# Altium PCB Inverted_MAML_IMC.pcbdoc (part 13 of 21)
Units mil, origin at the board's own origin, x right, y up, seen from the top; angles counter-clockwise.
Board outline 7677.1 x 6771.6 mil, 6 copper layers (Top Layer, Inner1, Inner2, Inner3, Inner4, Bottom Layer), stack 60.7 mil thick; 2732 components, 1531 nets, 7765 pads, 3705 vias.
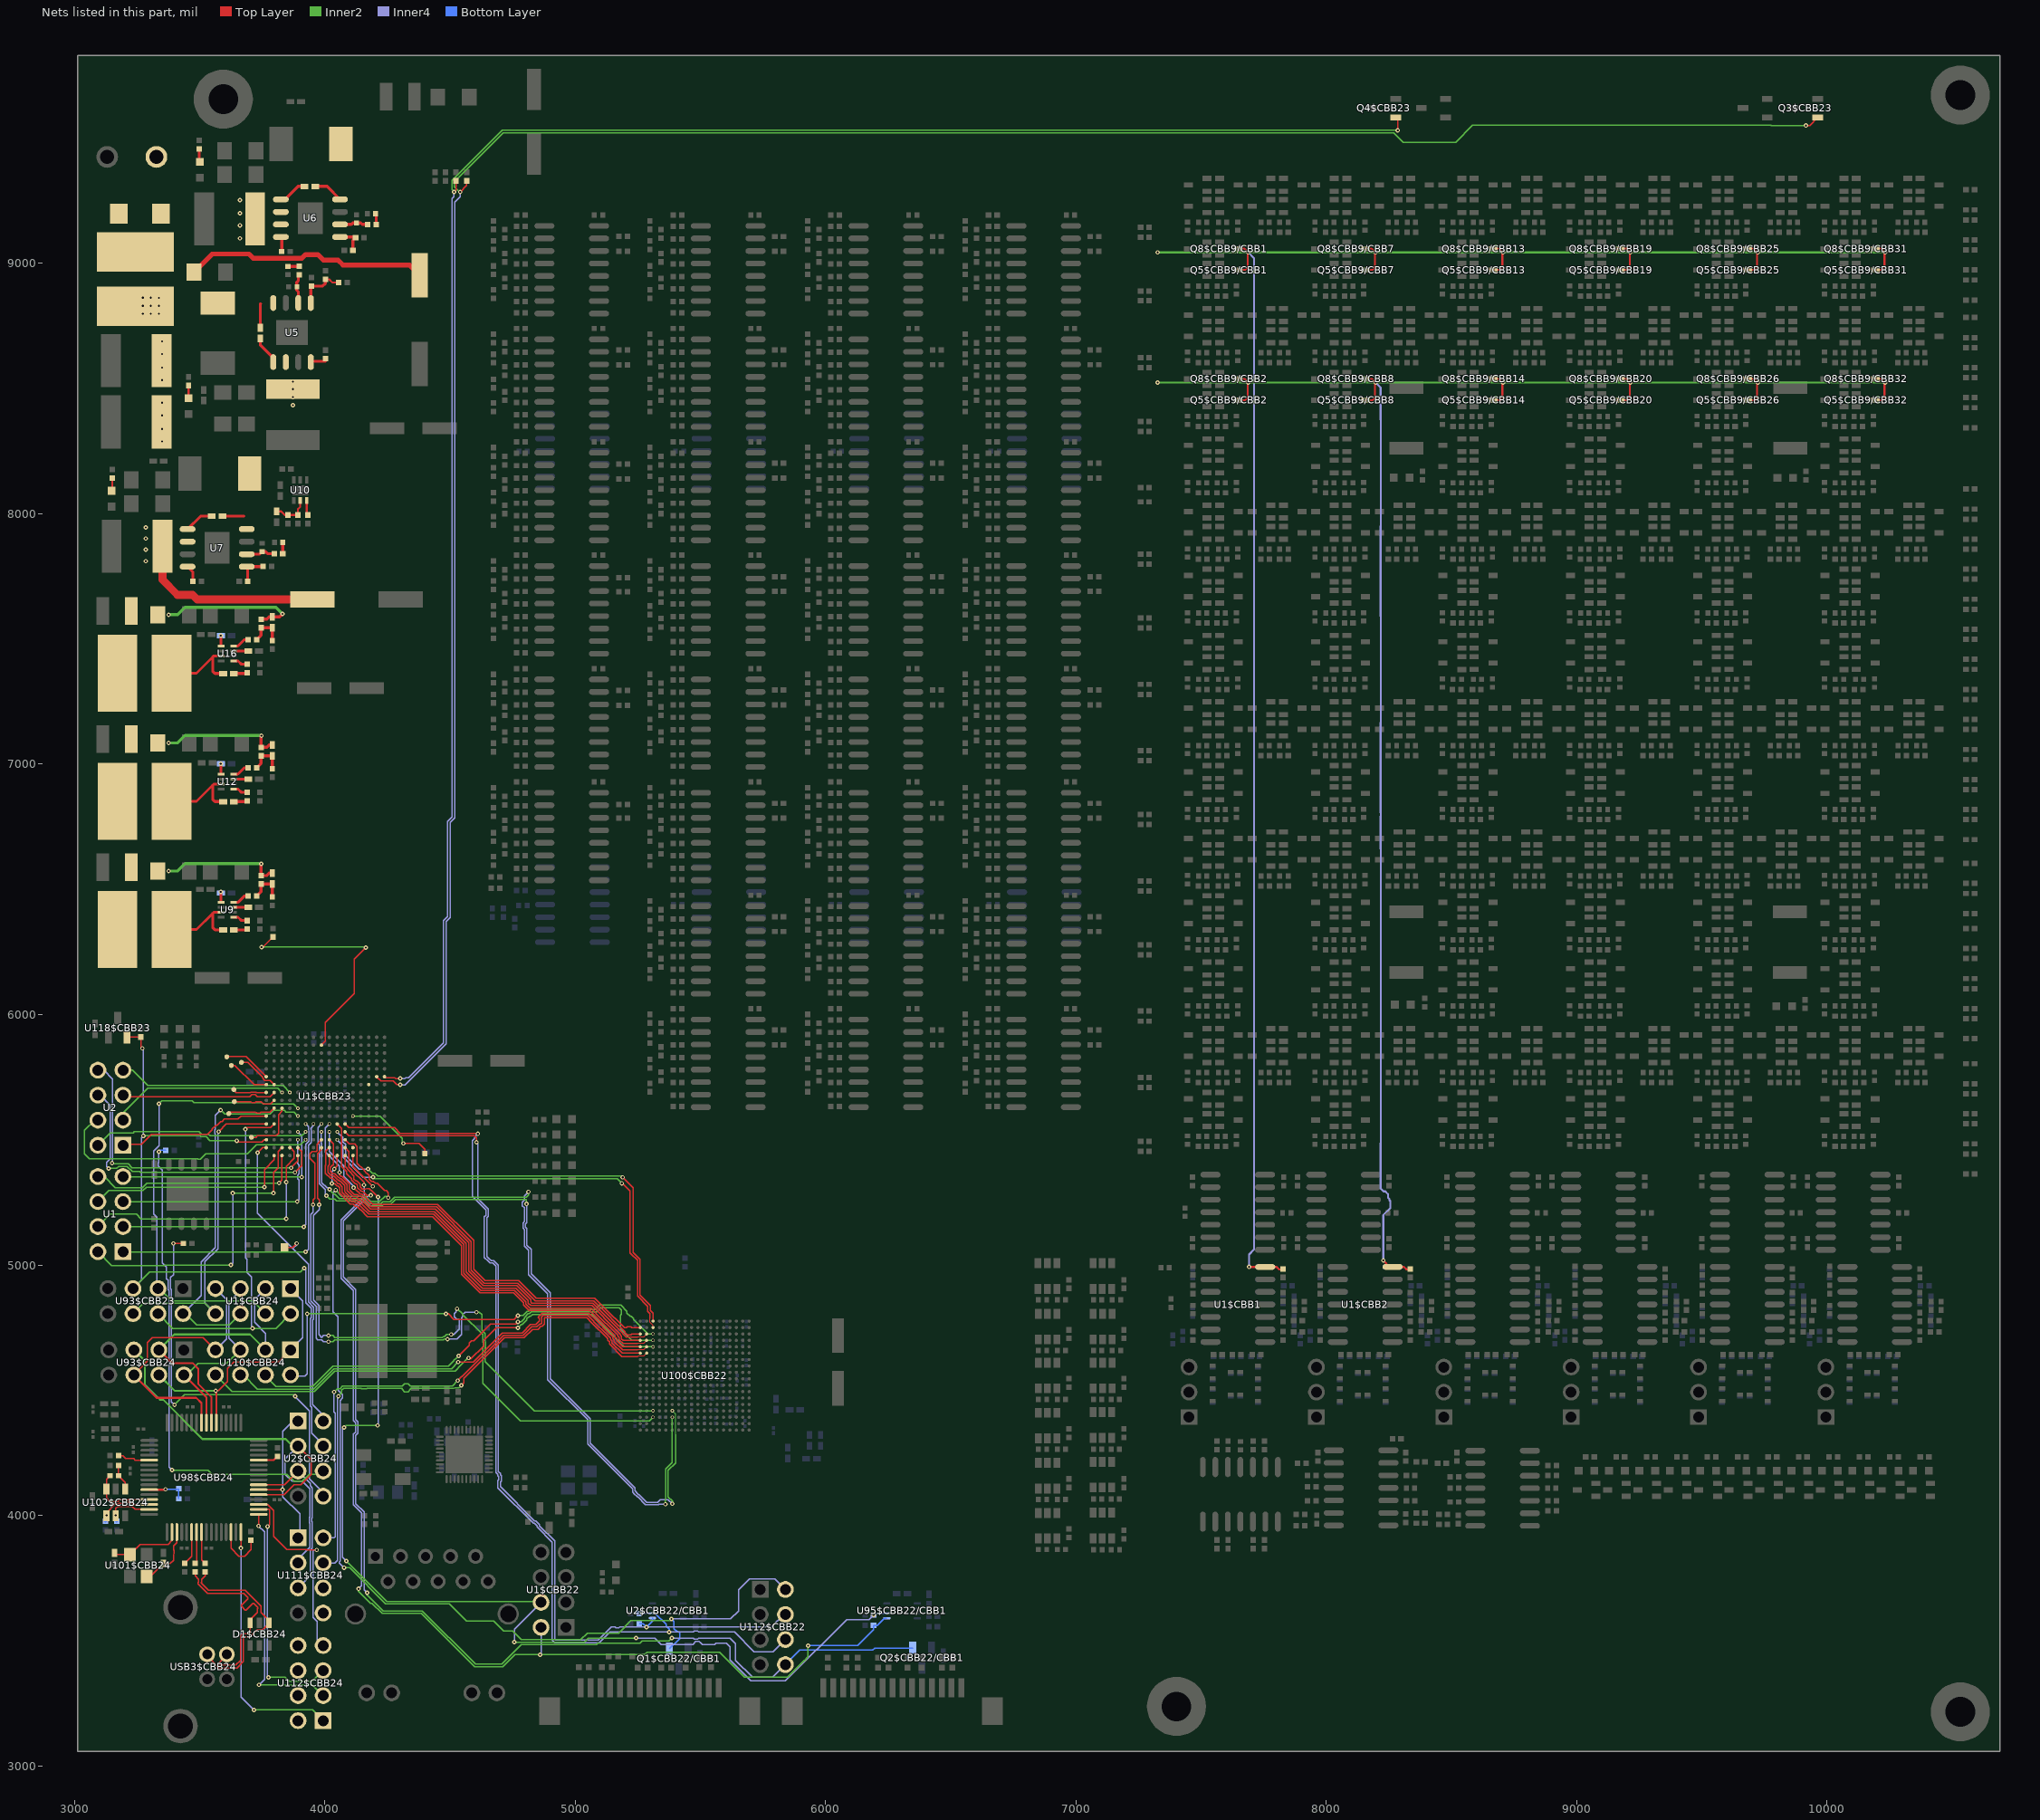
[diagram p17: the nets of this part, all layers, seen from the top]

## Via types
v1: diameter 17.7, hole 7.9, Top Layer to Bottom Layer, 3373 vias
v2: diameter 13.8, hole 7.9, Top Layer to Bottom Layer, 287 vias
v3: diameter 23.6, hole 11.8, Top Layer to Bottom Layer, 45 vias

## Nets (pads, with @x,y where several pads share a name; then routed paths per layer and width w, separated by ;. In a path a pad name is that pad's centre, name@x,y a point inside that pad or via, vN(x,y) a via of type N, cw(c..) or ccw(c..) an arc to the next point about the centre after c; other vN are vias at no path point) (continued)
$4I198\HEAT_3_EN: Q3$CBB23.1 R25$CBB23.2 U1$CBB23.F15 | length 9475.5
  Top Layer w4.7: U1$CBB23.F15@4207.6,5751.9 4224.2,5735.3 4273.2,5735.3 4288.4,5720.1 v1(4301.9,5720.1) ; v1(4541.4,9285.2) 4567,9310.8 R25$CBB23.2@4567,9329.8 ; v1(9916,9550.4) 9930.4,9550.4 Q3$CBB23.1@9962.6,9582.5
  Inner2 w4.7: v1(4541.4,9285.2) 4539.7,9285.2 4518.1,9306.7 4518.1,9326.8 4713.2,9521.9 8269.2,9521.9 8307.6,9483.4 8516.5,9483.4 8584.7,9551.7 9775.4,9551.7 9776.7,9550.4 v1(9916,9550.4)
  Inner4 w4.7: v1(4301.9,5720.1) 4303.4,5718.6 4320.2,5718.6 4484.5,5882.9 4484.5,6371 4501.5,6388 4501.5,6767.5 4519.5,6785.5 4519.5,9244.4 4541.4,9266.3 v1(4541.4,9285.2)
$4I198\HEAT_4_EN: Q4$CBB23.1 R26$CBB23.2 U1$CBB23.F16 | length 7724.7
  Top Layer w4.7: U1$CBB23.F16@4239.1,5751.9 4243.8,5747.2 4280.6,5747.2 4283.1,5744.7 v1(4301.9,5744.7) ; v1(4516.8,9285.2) 4524.8,9293.2 R26$CBB23.2@4524.8,9329.8 ; Q4$CBB23.1@8278,9582.5 8285.6,9574.9 v1(8285.6,9531.6)
  Inner2 w4.7: v1(4516.8,9285.2) 4516.8,9286.6 4508.4,9295 4508.4,9330.8 4709.2,9531.6 v1(8285.6,9531.6)
  Inner4 w4.7: v1(4301.9,5744.7) 4320.8,5744.7 4323,5746.9 4334.8,5746.9 4474.5,5886.6 4474.5,6375.2 4491.4,6392.1 4491.4,6771.6 4509.5,6789.7 4509.5,9259 4516.8,9266.3 v1(4516.8,9285.2)
$4I198\NSTATUS: R2$CBB23.1 U1$CBB23.B8 | length 943.5
  Top Layer w4.7: U1$CBB23.B8@3987.1,5877.9 4003,5893.8 4003,5968.5 4118.3,6083.9 4118.3,6221.7 v1(4164.4,6267.8)
  Top Layer w5.9: v1(3747.8,6269.8) 3753.8,6269.8 R2$CBB23.1@3793.9,6310
  Inner2 w4.7: v1(3747.8,6269.8) 4162.4,6269.8 v1(4164.4,6267.8)
$4I198\RX00_T20_N: U1$CBB23.R9 U100$CBB22.R17 | length 1772.9
  Top Layer w4.3: 5250.9,4686 5251.2,4686.3 5273.3,4686.3 U100$CBB22.R17@5285.9,4698.9
  Top Layer w4.7: U1$CBB23.R9@4018.6,5468.5 4004.2,5454 4004.2,5399 4002.8,5397.7 4002.8,5368.1 4003.2,5367.7 4003.2,5366.5 4024.1,5345.6 4032.2,5345.6 4042.9,5334.9 4043.7,5334.9 4053.7,5324.9 4057.7,5324.9 4069.8,5312.8 4069.8,5289.8 4072.9,5286.7 4072.9,5286.3 4106.8,5252.4 4118.6,5252.4 4126.5,5244.5 4133,5244.5 4148.2,5229.3 4149.3,5229.3 4175.4,5203.2 4434.4,5203.2 4555.9,5081.8 4555.9,4967.3 4625.1,4898 4758.8,4898 4803.6,4853.2 4803.6,4844 4819.7,4827.9 5063,4827.9 5104.5,4786.4 5104.5,4786.1 5142.5,4748.1 5142.8,4748.1 5170.1,4720.7 5170.1,4718 5176.1,4712 5176.1,4701.3 5191.4,4686 5250.9,4686
$4I198\RX00_T20_P: U1$CBB23.P9 U100$CBB22.T17 | length 1771.1
  Top Layer w4.3: 5250.9,4711.6 5251.2,4711.9 5273.3,4711.9 U100$CBB22.T17@5285.9,4724.5
  Top Layer w4.7: U1$CBB23.P9@4018.6,5500 4034.9,5483.7 4034.9,5400.2 4033.8,5399.1 4031.8,5399.1 4022.3,5389.6 4022.3,5376.2 4022.7,5375.8 4022.7,5374.6 4032.2,5365.1 4041.1,5365.1 4042.8,5363.4 4042.8,5362.5 4050.9,5354.4 4051.8,5354.4 4061.8,5344.4 4065.7,5344.4 4089.3,5320.9 4089.3,5297.9 4092.3,5294.8 4092.3,5294.3 4114.9,5271.8 4126.7,5271.8 4134.5,5263.9 4141.1,5263.9 4156.3,5248.8 4157.4,5248.8 4183.5,5222.7 4442.5,5222.7 4575.3,5089.8 4575.3,4975.4 4633.2,4917.5 4766.8,4917.5 4823,4861.3 4823,4852.1 4827.8,4847.3 5071,4847.3 5123.9,4794.4 5123.9,4794.1 5150.5,4767.5 5150.8,4767.5 5189.6,4728.8 5189.6,4726 5204.8,4710.8 5226.3,4710.8 5227,4711.6 5250.9,4711.6
$4I198\RX01_T20_N: U1$CBB23.M9 U100$CBB22.T18 | length 1782.6
  Top Layer w4.7: v1(4059.4,5369.7) 4059.4,5360.5 4065.8,5354.1 4069.8,5354.1 4099,5324.9 4099,5301.9 4102,5298.8 4102,5298.4 4118.9,5281.5 4130.7,5281.5 4138.6,5273.7 4145.1,5273.7 4160.3,5258.5 4161.4,5258.5 4187.5,5232.4 4446.5,5232.4 4585,5093.9 4585,4979.4 4637.2,4927.2 4770.9,4927.2 4841,4857 5075.1,4857 5133.7,4798.4 5133.7,4798.1 5154.6,4777.2 5154.9,4777.2 5199.3,4732.8 5199.3,4730.1 5208.8,4720.6 5222.2,4720.6 5226.2,4724.5 U100$CBB22.T18@5260.4,4724.5
  Inner4 w4.7: v2(4018.6,5563) 4002.8,5547.1 4002.8,5451.6 4059.4,5394.9 v1(4059.4,5369.7)
$4I198\RX01_T20_P: U1$CBB23.N9 U100$CBB22.U18 | length 1711.2
  Top Layer w4.7: v1(4115.2,5308.6) 4132.6,5291.3 4134.7,5291.3 4142.6,5283.4 4149.2,5283.4 4164.3,5268.2 4165.4,5268.2 4191.5,5242.1 4450.5,5242.1 4594.8,5097.9 4594.8,4983.4 4641.3,4936.9 4774.9,4936.9 4845.1,4866.8 5079.1,4866.8 5143.4,4802.5 5143.4,4802.2 5158.6,4787 5158.9,4787 5197,4748.8 5204.6,4748.8 5208.8,4753 5222.2,4753 5226.4,4748.8 5259.1,4748.8 U100$CBB22.U18@5260.4,4750.1
  Inner4 w4.7: v2(4018.6,5531.5) 4018.6,5453.8 4077,5395.4 4077,5353.2 4115.2,5315 v1(4115.2,5308.6)
$4I198\RX02_T20_N: U1$CBB23.T10 U100$CBB22.P18 | length 1716.8
  Top Layer w4.7: v1(4028.9,5325.2) 4039.7,5325.2 4049.7,5315.2 4053.6,5315.2 4060.1,5308.8 4060.1,5289.2 4059.6,5288.7 4059.6,5285.8 4102.8,5242.6 4114.6,5242.6 4122.4,5234.8 4129,5234.8 4144.2,5219.6 4145.3,5219.6 4171.4,5193.5 4430.4,5193.5 4546.1,5077.8 4546.1,4963.3 4621.1,4888.3 4754.8,4888.3 4793.9,4849.2 4793.9,4840 4815.7,4818.1 5058.9,4818.1 5094.8,4782.3 5094.8,4782 5138.4,4738.3 5138.7,4738.3 5160.4,4716.7 5160.4,4711.6 5166.4,4705.6 5166.4,4697.3 5190.3,4673.3 U100$CBB22.P18@5260.4,4673.3 ; v1(4038.5,5382.9) 4050.1,5394.5 U1$CBB23.T10@4050.1,5437
  Inner4 w4.7: v1(4028.9,5325.2) 4028.9,5373.3 v1(4038.5,5382.9)
$4I198\RX02_T20_P: U1$CBB23.T9 U100$CBB22.R18 | length 1689
  Top Layer w4.7: U1$CBB23.T9@4018.6,5437 4018.6,5399.7 4012.6,5393.7 4012.6,5372.2 4013,5371.8 4013,5370.6 4028.2,5355.4 4036.2,5355.4 4046.9,5344.7 4047.7,5344.7 4057.7,5334.6 4061.7,5334.6 4079.5,5316.8 4079.5,5293.8 4082.6,5290.8 4082.6,5290.3 4110.8,5262.1 4122.6,5262.1 4130.5,5254.2 4137.1,5254.2 4152.3,5239 4153.4,5239 4179.4,5213 4438.5,5213 4565.6,5085.8 4565.6,4971.3 4629.2,4907.8 4762.8,4907.8 4813.3,4857.3 4813.3,4848 4823.7,4837.6 5067,4837.6 5114.2,4790.4 5114.2,4790.1 5146.5,4757.8 5146.8,4757.8 5179.8,4724.8 5179.8,4722 5185.8,4716 5185.8,4705.3 5192.2,4698.9 U100$CBB22.R18@5260.4,4698.9
$4I198\RX03_T20_N: U1$CBB23.N10 U100$CBB22.V16 | length 1875.4
  Top Layer w4.7: v1(5190.1,5349.9) 5231.6,5308.4 5231.6,5050 5259.4,5022.2 5259.4,4879.6 5300.1,4838.9 5300.1,4818.7 5311.5,4807.3 U100$CBB22.V16@5311.5,4775.7
  Inner2 w4.7: v1(4173.4,5383.3) 4190.2,5366.5 4200.2,5366.5 4212.2,5354.6 5185.4,5354.6 v1(5190.1,5349.9)
  Inner4 w4.7: v2(4050.1,5531.5) 4073,5508.6 4073,5491.7 4083.1,5481.7 4083.1,5437.5 4137.3,5383.3 v1(4173.4,5383.3)
$4I198\RX03_T20_P: U1$CBB23.P10 U100$CBB22.U16 | length 1865.7
  Top Layer w4.3: 5298.6,4785.2 5298.9,4784.8 5298.9,4770.5 5311.5,4757.9 U100$CBB22.U16@5311.5,4750.1
  Top Layer w4.7: v1(5186.7,5326.2) 5188.3,5326.2 5219.5,5295 5219.5,5048.3 5223.5,5044.3 ; 5224.6,5043 5223.5,5044.3 ; 5298.6,4785.2 5298.6,4806.5 5290.4,4814.7 5290.4,4834.9 5249.6,4875.6 5249.6,5018.2 5223.5,5044.3
  Inner2 w4.7: v1(4193.5,5350.3) 4199,5344.9 5168,5344.9 v1(5186.7,5326.2)
  Inner4 w4.7: v2(4050.1,5500) 4073,5477.1 4073,5431.5 4154.2,5350.3 v1(4193.5,5350.3)
$4I198\RX04_T20_N: R134$CBB22/CBB1.1 U1$CBB22.2 U1$CBB23.R11 U95$CBB22/CBB1.5 | length 4432.3
  Top Layer w4.7: U1$CBB23.R11@4081.6,5468.5 4096.7,5453.4 4096.7,5392.1 4109.8,5379 4109.8,5377.3 4157.4,5329.7 v1(4157.4,5319.1)
  Inner2 w4.7: v1(4135.3,3706.7) 4135.3,3696.7 4183.5,3648.5 4189.5,3648.5 4229.6,3608.3 4386.2,3608.3 4598.7,3395.8 4711.5,3395.8 4759.4,3443.7 v1(4860.1,3443.7) 5277.8,3443.7 5287.8,3453.7 5576.9,3453.7 5677.3,3353.3 5848,3353.3 5916.1,3421.5 5917,3421.5 5926.5,3431 5926.5,3431.8 5930.3,3435.7 v1(5930.3,3479.8)
  Inner4 w4.7: v1(4135.3,3706.7) 4147.6,3719.1 4147.6,4009.9 4114.6,4043 4114.6,4324.1 4123,4332.5 4123,4370.1 4114.6,4378.5 4114.6,4898.3 4065.3,4947.6 4065.3,5180.5 4157.4,5272.6 v1(4157.4,5319.1) ; v1(4860.1,3443.7) 4864.3,3447.9 U1$CBB22.2@4864.3,3552.7
  Bottom Layer w4.7: v1(5930.3,3479.8) 6129.1,3479.8 6192.3,3543.1 R134$CBB22/CBB1.1@6192.3,3560.2 6206.1,3560.2 6235.3,3589.3 U95$CBB22/CBB1.5@6245.1,3589.3
$4I198\RX04_T20_P: R133$CBB22/CBB1.1 U1$CBB22.4 U1$CBB23.T11 U95$CBB22/CBB1.6 | length 4607.7
  Top Layer w4.7: U1$CBB23.T11@4081.6,5437 4081.6,5392.8 4100.1,5374.3 4100.1,5373.2 4117.2,5356.1 4117.2,5343.1 4125.8,5334.6 4129,5334.6 4141.1,5322.4 4141.1,5312.3 4150.6,5302.8 4164.1,5302.8 4166.6,5305.3 4177.7,5305.3 4185.5,5297.5 4187.1,5297.5 v1(4213.6,5271)
  Inner2 w4.7: v1(4077.6,4351.3) 4085.6,4359.3 v1(4211.7,4359.3) ; v1(4087.1,3817.2) 4247.7,3656.5 4860.5,3656.5 U1$CBB22.4@4864.3,3652.7 ; v1(4757.7,3493.9) 5036.8,3493.9 5052.9,3510 v1(5243.6,3510)
  Inner4 w4.7: v1(4077.6,4351.3) 4071.1,4344.8 4071.1,3833.2 v1(4087.1,3817.2) ; v1(4211.7,4359.3) 4213.6,4361.1 v1(4213.6,5271) ; v1(4757.7,3493.9) 4757.7,3546.1 U1$CBB22.4@4864.3,3652.7 ; v1(5243.6,3510) 5317.9,3510 5344,3483.9 5472.4,3483.9 5472.4,3486.4 5481.9,3495.9 5495.3,3495.9 5497.3,3493.9 5499.3,3493.9 5508.8,3484.4 5508.8,3483.9 5556.9,3483.9 5562,3489 5604.1,3489 5618.2,3474.9 5618.2,3422.5 5701.4,3339.3 5840,3339.3 6084.9,3584.3 6173.7,3584.3 6191.8,3602.3 v1(6192.3,3602.3)
  Bottom Layer w4.7: v1(6192.3,3602.3) 6199,3609 U95$CBB22/CBB1.6@6245.1,3609
$4I198\RX05_T20_N: R131$CBB22/CBB1.1 U1$CBB23.M11 U2$CBB22/CBB1.6 U112$CBB22.6 | length 3897.7
  Top Layer w4.7: U1$CBB23.M11@4081.6,5563 4096.6,5548 4278.4,5548 4301.2,5525.2 4610.3,5525.2 v1(4611.8,5523.8)
  Inner4 w4.7: v1(4611.8,5523.8) 4605.4,5517.4 4605.4,5512 4590,5496.6 4590,5273.9 4643.9,5220 4643.9,5198.5 4638,5192.6 4638,5052.1 4637.6,5051.7 4637.6,5030.2 4652.8,5015 4653.7,5015 4661.3,5007.4 4671.5,5007.4 4683.7,4995.2 4683.7,4171.2 4691.8,4163.2 4691.8,4158.3 4695.3,4154.7 4695.3,4141.3 4691.8,4137.7 4691.8,4110.3 4834.2,3967.9 4838.7,3967.9 4848.2,3958.4 4848.2,3953.8 4908.6,3893.5 4908.6,3501.9 4918.6,3491.9 5097,3491.9 5139.2,3534.1 v1(5376.1,3534.1) 5471.7,3534.1 5475.8,3538.2 5489.3,3538.2 5493.5,3534.1 5637.2,3534.1 5715.5,3455.7 5791.4,3455.7 U112$CBB22.6@5839.8,3504.1
  Bottom Layer w4.7: R131$CBB22/CBB1.1@5256.5,3608.2 5308,3608.2 U2$CBB22/CBB1.6@5309.4,3609.6 5319.2,3609.6 5364.1,3564.8 5364.1,3558.1 5376.1,3546.1 v1(5376.1,3534.1)
$4I198\RX05_T20_P: Q2$CBB22/CBB1.1 U1$CBB23.M10 U112$CBB22.8 | length 4539.2
  Top Layer w4.7: U1$CBB23.M10@4050.1,5563 4067,5546.1 4067,5393.6 4087.1,5373.6 4087.1,5365.2 4107.5,5344.8 4107.5,5339.1 4109.2,5337.4 4109.2,5337.1 4121.5,5324.8 4125,5324.8 4131.4,5318.4 4131.4,5308.3 4146.6,5293.1 4153.2,5293.1 4168.4,5277.9 v1(4183.7,5277.9)
  Inner2 w4.7: v1(4169.4,3690.7) 4169.4,3682.7 4233.8,3618.3 4390.3,3618.3 4603.1,3405.6 4707.5,3405.6 4785.8,3483.9 5085,3483.9 5091,3489.9 5259.7,3489.9 5267.7,3497.9 5374.1,3497.9 v1(5386.2,3510)
  Inner4 w4.7: v1(4169.4,3690.7) 4157.4,3702.7 4157.4,4013.9 4124.3,4047 4124.3,4320 4132.7,4328.4 4132.7,4374.1 4124.3,4382.5 4124.3,4902.4 4075,4951.6 4075,5176.5 4176.5,5277.9 v1(4183.7,5277.9) ; v1(5386.2,3510) 5471.7,3510 5475.8,3505.8 5489.3,3505.8 5493.5,3510 5619.1,3510 5641.2,3487.9 5641.2,3421.6 5709.4,3353.3 5789,3353.3 U112$CBB22.8@5839.8,3404.1
  Bottom Layer w4.7: U112$CBB22.8@5839.8,3404.1 5897.4,3461.8 6189.3,3461.8 6197.4,3469.8 6347.5,3469.8 Q2$CBB22/CBB1.1@6348.7,3471
$4I198\RX06_T20_N: Q1$CBB22/CBB1.1 U1$CBB23.P11 U112$CBB22.2 | length 4312.2
  Top Layer w4.7: U1$CBB23.P11@4081.6,5500 4097.9,5483.7 4119.2,5483.7 4129.3,5473.7 4129.3,5406.7 4157.2,5378.8 4157.2,5376.6 4166.7,5367.1 4168.9,5367.1 4178.1,5357.9 4177.3,5357 4177.3,5343.6 4186.8,5334.1 4194.8,5334.1 4202.8,5326.1 4209.9,5326.1 4239,5297 4245.7,5297 4253.7,5288.9 v1(4253.7,5268.7)
  Inner2 w4.7: v1(4043.9,5299) 4068,5274.9 4163.8,5274.9 4183.9,5254.8 4220.3,5254.8 4240.4,5274.9 4247.6,5274.9 v1(4253.7,5268.7) ; v1(4077,3791.1) 4099.4,3791.1 4243.7,3646.8 4498.4,3646.8 4567,3578.2 4675.4,3578.2 4715.6,3538.1 4751.7,3538.1 4785.8,3503.9 5022.8,3503.9 5048.9,3530 5173.3,3530 5223.5,3580.2 5378.1,3580.2 v1(5384.2,3586.3)
  Inner4 w4.7: v1(4043.9,5299) 4032.9,5288 4032.9,4813.1 4053,4793 4053,4500.7 4071.3,4482.4 4071.3,4468.9 4061.4,4459 4061.4,3816.5 4059.3,3814.5 4059.3,3808.8 v1(4077,3791.1) ; v1(5384.2,3586.3) 5621.1,3586.3 5653.2,3618.4 5653.2,3702.5 5697.4,3746.7 5797.2,3746.7 U112$CBB22.2@5839.8,3704.1
  Bottom Layer w4.7: Q1$CBB22/CBB1.1@5376.9,3467 5417.6,3507.7 5417.6,3530.7 5414.3,3534.1 5408.3,3534.1 5394.2,3548.1 5394.2,3576.2 v1(5384.2,3586.3)
$4I198\RX06_T20_P: R132$CBB22/CBB1.1 U1$CBB23.N11 U2$CBB22/CBB1.5 U112$CBB22.4 | length 3730.1
  Top Layer w4.7: U1$CBB23.N11@4081.6,5531.5 4081.6,5531.3 4097.1,5515.8 4296.8,5515.8 4297.1,5515.5 4597.1,5515.5 4606.2,5506.4 v1(4606.2,5489.9)
  Inner4 w4.7: v1(4606.2,5489.9) 4612.7,5483.4 4612.7,5264.9 4653.6,5224 4653.6,5194.5 4647.8,5188.6 4647.8,5048.1 4647.3,5047.7 4647.3,5034.2 4656.8,5024.7 4657.7,5024.7 4665.3,5017.1 4675.5,5017.1 4693.5,4999.2 4693.5,4175.3 4701.5,4167.2 4701.5,4162.3 4705,4158.7 4705,4137.3 4701.5,4133.7 4701.5,4114.3 4838.2,3977.6 4842.8,3977.6 4858,3962.4 4858,3957.9 4918.3,3897.5 4918.3,3505.9 4922.4,3501.9 5093.3,3501.9 5145.5,3554.1 5160.3,3554.1 5162.6,3551.8 5176,3551.8 5178.4,3554.1 v1(5285.8,3554.1) 5784,3554.1 5834,3604.1 U112$CBB22.4@5839.8,3604.1
  Bottom Layer w4.7: R132$CBB22/CBB1.1@5256.5,3568 5271.9,3568 v1(5285.8,3554.1) 5309.4,3577.8 U2$CBB22/CBB1.5@5309.4,3589.9
$4I198\RX07_T20_N: U1$CBB23.R12
$4I198\RX07_T20_P: U1$CBB23.T12 | length 156
  Top Layer w4.7: U1$CBB23.T12@4113.1,5437 4113.1,5392.9 v1(4192.2,5313.8)
$4I198\T20_CDI2: R22$CBB23.2 U2$CBB24.8 | length 1641
  Top Layer w4.7: v1(3396.4,5086.1) R22$CBB23.2@3435.6,5086.1
  Inner2 w4.7: v1(3400.4,4441.6) 3440.6,4481.8 3876.3,4481.8 v1(3882.3,4475.7)
  Inner4 w4.7: v1(3396.4,5086.1) 3396.4,4961.7 3385,4950.3 3385,4904.7 3388.4,4901.3 3388.4,4453.6 v1(3400.4,4441.6) ; v1(3882.3,4475.7) 3882.3,4473.7 3938.5,4417.5 3938.5,4146.5 3993.8,4091.1 U2$CBB24.8@3993.8,4076.8
$4I198\T20_CDI3: R21$CBB23.2 U2$CBB24.6 | length 1964
  Inner2 w4.7: v1(3390.4,4180.6) 3534.9,4180.6 3551,4164.5 3848.3,4164.5 3876.9,4135.9 3910.7,4135.9 3939.3,4164.5 3981.6,4164.5 U2$CBB24.6@3993.8,4176.8
  Inner4 w4.7: v1(3337.6,5452.2) 3337.6,5410.1 3336,5408.5 3336,5395.1 3352.2,5378.9 3352.2,5007.8 3368.3,4991.8 3368.3,4945.6 3374.6,4939.3 3374.6,4923.3 3375.3,4922.6 3375.3,4900.7 3378.3,4897.7 3378.3,4678.2 3378.7,4677.8 3378.7,4544 3378.3,4543.6 3378.3,4192.6 v1(3390.4,4180.6)
  Bottom Layer w4.7: v1(3337.6,5452.2) 3343,5457.6 R21$CBB23.2@3365.3,5457.6
$4I198\T20_CLK8: U1$CBB23.G14
$4I198\T20_CONDONE: LED12$CBB23.1 U1$CBB23.R1 U2$CBB24.2 | length 1309.6
  Top Layer w4.7: v1(3732,5448.3) 3753.4,5469.6 3765.5,5469.6 U1$CBB23.R1@3766.7,5468.5 ; LED12$CBB23.1@3839.6,5070.6 3872.8,5070.6 v1(3888.3,5086.1)
  Inner4 w4.7: v1(3732,5448.3) 3732,5206.3 3873,5065.3 ; v1(3888.3,5086.1) 3888.3,5080.6 3873,5065.3 ; U2$CBB24.2@3993.8,4376.8 3993.8,4400.1 3952.2,4441.6 3952.2,4780.9 3956.3,4784.9 3956.3,4831.2 3935.1,4852.3 3935.1,5003.2 3873,5065.3
$4I198\T20_CRESET_N: R1$CBB23.1 U1$CBB23.P1 U2$CBB24.4 U93$CBB23.5 U118$CBB23.2 | length 3050.5
  Top Layer w4.7: U118$CBB23.2@3210.9,5908.1 3213.2,5910.4 R1$CBB23.1@3265.9,5910.4 3265.9,5871.2 v1(3271.9,5865.2) ; v1(3648.9,5496.2) 3654.2,5490.9 3750.2,5490.9 3759.2,5500 U1$CBB23.P1@3766.7,5500
  Inner2 w4.7: U93$CBB23.5@3234.5,4905.7 3300.5,4971.7 3902.8,4971.7 v1(3918.9,4987.8) ; v1(3275.9,5515.7) 3501.2,5515.7 3504.8,5512.1 3526.4,5512.1 3542.3,5496.2 v1(3648.9,5496.2)
  Inner4 w4.7: U93$CBB23.5@3234.5,4905.7 3267.9,4939.1 3267.9,5507.6 v1(3275.9,5515.7) 3275.9,5861.2 v1(3271.9,5865.2) ; v1(3918.9,4987.8) 3925.4,4981.3 3925.4,4848.3 3946.5,4827.1 3946.5,4789 3942.5,4785 3942.5,4437.6 3948.5,4431.6 3948.5,4329.2 3993.8,4283.9 U2$CBB24.4@3993.8,4276.8
$4I198\T20_IO_1: U1$CBB23.H4 U2.7 | length 703.7
  Inner2 w4.7: U2.7@3194.4,5778.2 3232.4,5778.2 3294.3,5716.3 3833.8,5716.3 v2(3861.1,5688.9)
$4I198\T20_IO_2: U1$CBB23.H2 U2.5 | length 620.2
  Top Layer w4.7: U2.5@3194.4,5678.2 3200.2,5672.4 3668.6,5672.4 3668.8,5672.6 3682.2,5672.6 3682.3,5672.4 3700.6,5672.4 3708.9,5680.8 3722.3,5680.8 3730.7,5672.4 3781.7,5672.4 U1$CBB23.H2@3798.2,5688.9
$4I198\T20_IO_3: U1$CBB23.H3 U2.3 | length 712.6
  Inner2 w4.7: U2.3@3194.4,5578.2 3194.4,5607 3294,5706.6 3812,5706.6 v2(3829.6,5688.9)
$4I198\T20_IO_4: U1$CBB23.L1 U2.1 | length 622.6
  Top Layer w4.7: U2.1@3194.4,5478.2 3198,5481.7 3267.9,5481.7 3308,5521.9 3533.2,5521.9 3551.1,5539.8 3551.1,5543.4 3566.3,5558.6 3570,5558.6 3584,5572.7 3589.6,5572.7 3599.3,5582.4 3653.7,5582.4 3665.7,5594.5 U1$CBB23.L1@3766.7,5594.5
$4I198\T20_IO_5: TP1.1 U1$CBB23.H1 | length 134.7
  Top Layer w4.7: TP1.1@3637.3,5698.5 3646.9,5688.9 3703.3,5688.9 3704.9,5690.5 3726.4,5690.5 3727.9,5688.9 U1$CBB23.H1@3766.7,5688.9
$4I198\T20_IO_6: TP2.1 U1$CBB23.G1 | length 171.1
  Top Layer w4.7: TP2.1@3627.3,5796.9 3641.3,5796.9 3717.8,5720.4 U1$CBB23.G1@3766.7,5720.4
$4I198\T20_IO_7: TP3.1 U1$CBB23.J2 | length 170.8
  Top Layer w4.7: TP3.1@3641.3,5652.4 3704.7,5652.4 3708.9,5648.2 3722.3,5648.2 3726.5,5652.4 3745.7,5652.4 3755.8,5642.3 3783,5642.3 U1$CBB23.J2@3798.2,5657.4
$4I198\T20_IO_8: TP4.1 U1$CBB23.K2 | length 190.8
  Top Layer w4.7: TP4.1@3617.2,5610.2 3722.3,5610.2 3724.8,5607.7 3727.7,5607.7 3729.1,5606.2 3742.6,5606.2 3746.6,5610.2 3782.4,5610.2 U1$CBB23.K2@3798.2,5625.9
$4I198\T20_IO_11: TP5.1 U1$CBB23.F1 | length 189.1
  Top Layer w4.7: TP5.1@3611.2,5833.1 3685.5,5833.1 U1$CBB23.F1@3766.7,5751.9
$4I198\T20_IO_12: TP6.1 U1$CBB23.G2 | length 170
  Top Layer w4.7: TP6.1@3667.4,5809 3693.5,5809 3752.2,5750.3 3752.2,5745.9 3760.7,5737.5 3765,5737.5 3765.8,5736.7 3781.9,5736.7 U1$CBB23.G2@3798.2,5720.4
$4I198\T20_IO_13: TP7.1 U1$CBB23.K3 | length 220.8
  Top Layer w4.7: TP7.1@3707.6,5509.8 3725.5,5509.8 3731.5,5515.8 3806,5515.8 3815.9,5525.7 3815.9,5600.2 3829.6,5613.9 U1$CBB23.K3@3829.6,5625.9
$4I198\T20_TCK: U1$CBB23.M2 U1$CBB24.2 U93$CBB23.4 | length 1508.2
  Top Layer w4.7: v1(3683.5,5541.9) 3689.5,5548 3783.2,5548 U1$CBB23.M2@3798.2,5563
  Inner2 w4.7: U93$CBB23.4@3334.5,4805.7 3393.3,4746.8 v1(3711.6,4746.8) 3804.8,4746.8 U1$CBB24.2@3863.6,4805.7
  Inner4 w4.7: v1(3683.5,5541.9) 3683.5,5027.9 3689.5,5021.9 3689.5,4969.7 3707.6,4951.6 3707.6,4750.8 v1(3711.6,4746.8)
$4I198\T20_TDI: U1$CBB23.K5 U1$CBB24.4 U93$CBB23.3 | length 1796.3
  Inner2 w4.7: U93$CBB23.3@3334.5,4905.7 3339.9,4905.7 3388.7,4856.9 3712.3,4856.9 U1$CBB24.4@3763.6,4805.7 ; v1(3338.1,5644.3) 3350.2,5656.4 3470.7,5656.4 3478.7,5648.3 3749.8,5648.3 3755.2,5643 3875.6,5643 v2(3892.6,5625.9)
  Inner4 w4.7: U93$CBB23.3@3334.5,4905.7 3330.1,4910 3330.1,5190.6 3318.1,5202.6 3318.1,5455.6 3338.1,5475.7 v1(3338.1,5644.3)
$4I198\T20_TDO: U1$CBB23.L5 U1$CBB24.6 U93$CBB23.2 | length 1473.9
  Inner2 w4.7: U93$CBB23.2@3434.5,4805.7 3444,4805.7 3488.7,4760.9 3618.8,4760.9 U1$CBB24.6@3663.6,4805.7 ; v1(3584.5,5618.9) 3601.2,5602.2 3781.9,5602.2 3796.6,5616.9 3838.9,5616.9 3845.6,5610.2 3876.9,5610.2 v2(3892.6,5594.5)
  Inner4 w4.7: U93$CBB23.2@3434.5,4805.7 3506.8,4878 3506.8,5012.5 3563.3,5069 3563.3,5523.5 3560.9,5526 3560.9,5539.4 3563.3,5541.9 3563.3,5597.8 v1(3584.5,5618.9)
$4I198\T20_TMS: U1$CBB23.M1 U1$CBB24.8 U93$CBB23.6 | length 1333.6
  Top Layer w4.7: v1(3577.1,5532.7) 3607.4,5563 U1$CBB23.M1@3766.7,5563
  Inner2 w4.7: U93$CBB23.6@3234.5,4805.7 3276,4847.2 3522.1,4847.2 U1$CBB24.8@3563.6,4805.7
  Inner4 w4.7: U1$CBB24.8@3563.6,4805.7 3520.9,4848.4 3520.9,5012.8 3573.1,5065 3573.1,5528.7 v1(3577.1,5532.7)
$4I198\TEST_N: R4$CBB23.1 U1$CBB23.L12 | length 368.8
  Top Layer w4.7: v1(4314,5485.7) 4376.2,5485.7 4400.3,5461.6 R4$CBB23.1@4400.3,5444.5
  Inner2 w4.7: v2(4113.1,5594.5) 4221.3,5594.5 4310,5505.8 4310,5489.7 v1(4314,5485.7)
$4I198\TX02_T20_N: U1$CBB23.R4 U1.4 | length 1085.8
  Top Layer w4.7: v1(3846.8,5331.1) 3846.8,5394 3878.3,5425.5 3878.3,5453.6 3863.4,5468.5 U1$CBB23.R4@3861.1,5468.5
  Inner2 w4.7: U1.4@3094.4,5153.2 3143.9,5202.6 3247.8,5202.6 3265.9,5184.5 v1(3846.8,5184.5)
  Inner4 w4.7: v1(3846.8,5184.5) v1(3846.8,5331.1)
$4I198\TX02_T20_P: U1$CBB23.R3 U1.2 | length 1203.2
  Top Layer w4.7: v1(3795.9,5286.9) 3795.9,5369.3 3814,5387.3 3814,5452.8 U1$CBB23.R3@3829.6,5468.5
  Inner2 w4.7: U1.2@3094.4,5053.2 3149.8,4997.8 3358.2,4997.8 3360.2,4999.8 v1(3625.3,4999.8) ; v1(3633.3,5286.9) v1(3795.9,5286.9)
  Inner4 w4.7: v1(3625.3,4999.8) 3633.3,5007.8 v1(3633.3,5286.9)
$4I198\TX03_T20_N: U1$CBB23.T3 U1.8 | length 864.1
  Top Layer w4.7: v1(3818,5327.1) 3829.6,5338.7 U1$CBB23.T3@3829.6,5437
  Inner2 w4.7: U1.8@3094.4,5353.2 3119.3,5353.2 3163.5,5309 3271.9,5309 3290,5327.1 v1(3818,5327.1)
$4I198\TX03_T20_P: U1$CBB23.T2 U1.6 | length 831.3
  Top Layer w4.7: v1(3759.8,5310.9) 3759.8,5381.3 3798.2,5419.6 U1$CBB23.T2@3798.2,5437
  Inner2 w4.7: U1.6@3094.4,5253.2 3138.2,5297 3273.6,5297 3287.5,5310.9 v1(3759.8,5310.9)
$4I198\TX04_T20_N: U1$CBB23.P5 U1.5 | length 953.9
  Inner2 w4.7: U1.5@3194.4,5253.2 3194.8,5252.8 v1(3890.3,5252.8)
  Inner4 w4.7: v1(3890.3,5252.8) 3898.3,5260.8 3898.3,5338.3 3892.2,5344.5 3892.2,5357.9 3898.3,5364.1 3898.3,5399.4 3892.6,5405.1 v2(3892.6,5500)
$4I198\TX04_T20_P: U1$CBB23.N5 U1.7 | length 901.6
  Inner2 w4.7: U1.7@3194.4,5353.2 3196.5,5351.2 v1(3908.4,5351.2)
  Inner4 w4.7: v2(3892.6,5531.5) 3908.4,5515.7 v1(3908.4,5351.2)
$4I198\TX05_T20_N: U1$CBB23.M7 U1.1 | length 1256.2
  Inner2 w4.7: U1.1@3194.4,5053.2 3195.6,5052 v1(3924.4,5052)
  Inner4 w4.7: v1(3924.4,5052) 3935.1,5062.7 3935.1,5478.3 3946.6,5489.8 3946.6,5540.8 3944.5,5542.8 3944.5,5545.9 3955.6,5557.1 v2(3955.6,5563)
$4I198\TX05_T20_P: U1$CBB23.M6 U1.3 | length 1147.2
  Inner2 w4.7: U1.3@3194.4,5153.2 3195.2,5152.4 v1(3916.4,5152.4)
  Inner4 w4.7: v1(3916.4,5152.4) 3925.4,5161.4 3925.4,5482.3 3937.5,5494.4 3937.5,5537 3935.5,5539.1 3935.5,5551.6 v2(3924.1,5563)
$4I198\TX06_T20_N: U1$CBB23.P6 U2.4 | length 1089.2
  Inner2 w4.7: U2.4@3094.4,5578.2 3081.3,5578.2 3041,5537.9 3041,5443.5 3061.1,5423.5 3491.9,5423.5 3493.9,5421.5 3503.6,5421.5 3525.7,5443.5 3691.5,5443.5 3727.7,5479.7 3903.9,5479.7 v2(3924.1,5500)
$4I198\TX06_T20_P: U1$CBB23.N6 U2.2 | length 865.1
  Inner2 w4.7: U2.2@3094.4,5478.2 3144.1,5527.9 3235.7,5527.9 3239.8,5531.9 3498.8,5531.9 3508.8,5521.9 3536.9,5521.9 3543,5515.8 3908.5,5515.8 v2(3924.1,5531.5)
$4I198\TX07_T20_N: U1$CBB23.T5 U2.8 | length 1193.2
  Top Layer w4.7: v1(3865.7,5387.9) 3892.6,5414.8 U1$CBB23.T5@3892.6,5437
  Inner2 w4.7: v1(3150.8,5407.2) 3154.3,5403.7 3215.4,5403.7 3231.3,5387.9 v1(3865.7,5387.9)
  Inner4 w4.7: U2.8@3094.4,5778.2 3118,5778.2 3153.1,5743 3153.1,5409.5 v1(3150.8,5407.2)
$4I198\TX07_T20_P: U1$CBB23.R5 U2.6 | length 1201.5
  Top Layer w4.7: v1(3881.4,5370) 3908.4,5397.1 3908.4,5452.7 U1$CBB23.R5@3892.6,5468.5
  Inner2 w4.7: v1(3137.4,5385.3) 3168.8,5385.3 3177.5,5394 3211.4,5394 3231.8,5373.6 3261.5,5373.6 3265.1,5370 v1(3881.4,5370)
  Inner4 w4.7: U2.6@3094.4,5678.2 3103.5,5678.2 3143.4,5638.3 3143.4,5423.5 3129.3,5409.4 3129.3,5393.3 v1(3137.4,5385.3)
$4I198\TX11_T20_N: U1$CBB23.N8 U100$CBB22.C13 | length 3004.2
  Inner2 w4.7: v1(4020.2,5301.5) 4020.2,5299.7 4037.1,5282.8 4040.2,5282.8 4057.8,5265.2 4159.8,5265.2 4179.9,5245.1 4224.3,5245.1 4231.7,5252.5 4260.5,5252.5 4278.6,5270.7 4805.9,5270.7 4814.1,5278.9 v1(4814.1,5292.2) ; v1(5360.6,4044.6) 5360.6,4063.5 5362.6,4065.5 5362.4,4065.7 5362.4,4184.9 5388.3,4210.8 v2(5388.3,4391.9)
  Inner4 w4.7: v2(3987.1,5531.5) 3987.1,5485 3988.4,5483.7 3988.4,5329.1 4009.6,5307.9 4019.1,5307.9 4022.1,5304.8 4022.1,5303.5 v1(4020.2,5301.5) ; v1(4814.1,5292.2) 4798.2,5276.2 4798.2,5258.7 4789.7,5250.2 4789.7,5236.7 4798.2,5228.3 4798.2,5173.8 4792.5,5168.1 4792.5,5146.6 4798.2,5140.9 4798.2,5074.4 4814.6,5058 4814.6,4961.6 4890.2,4886 4890.2,4542.6 5051,4381.8 5051,4284.8 5229.9,4105.9 5229.9,4094.2 5234.5,4089.6 5234.5,4088.3 5249.7,4073.1 5251.1,4073.1 5281.4,4042.7 5334,4042.7 5335.9,4044.6 v1(5360.6,4044.6)
$4I198\TX11_T20_P: U1$CBB23.M8 U100$CBB22.D13 | length 3055.2
  Inner2 w3.9: v2(5388.3,4417.4) 5401.1,4404.6 5401.1,4361 5402.2,4359.8 5402.2,4323 5401.3,4322.1
  Inner2 w4.7: v1(4006.6,5277.1) 4019.9,5263.8 4039.9,5263.8 4048.3,5255.4 4155.8,5255.4 4175.9,5235.4 4228.3,5235.4 4235.7,5242.8 4264.5,5242.8 4282.7,5260.9 4805.9,5260.9 v1(4805.9,5243.5) ; v1(5388.6,4046.5) 5388.6,4057.1 5372.1,4073.6 5372.1,4180.6 5401.3,4209.8 5401.3,4322.1
  Inner4 w4.7: v2(3987.1,5563) 3973.7,5549.6 3973.7,5484.6 3978.7,5479.7 3978.7,5325.1 4002.8,5301 4002.8,5281 v1(4006.6,5277.1) ; v1(4805.9,5243.5) 4807.9,5241.5 4807.9,5169.7 4802.3,5164.1 4802.3,5150.6 4807.9,5145 4807.9,5078.4 4824.3,5062 4824.3,4965.7 4900.6,4889.4 4900.6,4546 5060.9,4385.7 5060.9,4288.9 5239.6,4110.2 5239.6,4098.3 5244.3,4093.6 5244.3,4092.3 5253.8,4082.8 5255.1,4082.8 5285.5,4052.4 5330,4052.4 5340.9,4063.3 5371.7,4063.3 v1(5388.6,4046.5)
$4I198\TX12_T20_N: U1$CBB23.P8 U100$CBB22.D16 | length 2554
  Top Layer w4.7: v1(3953.7,5240.6) 3953.7,5259.4 3961.2,5266.9 3961.2,5406.8 3941.9,5426.1 3941.9,5444.2 3950.6,5452.9 3965.8,5452.9 3969.4,5456.5 3969.4,5482.2 U1$CBB23.P8@3987.1,5500
  Inner2 w4.7: v1(4015,4693.5) 4033.9,4693.5 4041.3,4700.9 4474.6,4700.9 4477.3,4703.6 v1(4490.8,4703.6) ; v1(4606.2,4811.3) 4617.5,4811.3 4627.2,4801.5 4627.2,4740.5 4640.9,4726.8 4640.9,4696.7 4643.1,4694.5 4643.1,4670.6 4640.9,4668.4 4640.9,4614.6 4838.1,4417.4 v2(5311.5,4417.4)
  Inner4 w4.7: v1(3953.7,5240.6) 3953.7,5210.8 3944.8,5201.9 3944.8,4856.3 3966,4835.2 3966,4707.6 3972.6,4700.9 3988.7,4700.9 3996.1,4693.5 v1(4015,4693.5) ; v1(4490.8,4703.6) 4527.8,4703.6 4546.6,4722.4 4546.6,4787.8 4551.1,4792.3 4551.1,4801.5 4560.8,4811.3 v1(4606.2,4811.3)
$4I198\TX12_T20_P: U1$CBB23.R8 U100$CBB22.C16 | length 2549.7
  Top Layer w4.7: v1(3978.3,5240.6) 3978.3,5259.4 3970.9,5266.9 3970.9,5444.3 3987.1,5460.5 U1$CBB23.R8@3987.1,5468.5
  Inner2 w4.7: v1(4015,4718.1) 4033.9,4718.1 4041.3,4710.7 4470.6,4710.7 4473.2,4713.3 4477.3,4713.3 4486.5,4722.6 v1(4505.4,4722.6) ; v1(4528.7,4825.3) 4538.7,4815.2 4541.6,4815.2 4551.1,4805.7 4551.1,4802.9 4631.2,4722.8 4631.2,4692.7 4633.4,4690.5 4633.4,4674.6 4631.2,4672.4 4631.2,4528 4781.8,4377.4 5297,4377.4 v2(5311.5,4391.9)
  Inner4 w4.7: v1(3978.3,5240.6) 3978.3,5221.7 3954.6,5197.9 3954.6,4860.4 3976.7,4838.3 3976.7,4722.7 3988.7,4710.7 3996.1,4718.1 v1(4015,4718.1) ; v1(4505.4,4722.6) 4515.3,4722.6 4536.9,4744.1 4536.9,4782.8 4528.1,4782.8 4518.6,4792.3 4518.6,4805.7 4525.1,4812.2 4525.1,4821.8 v1(4528.7,4825.3)
$4I280\$1N130248: R211$CBB24.1 R212$CBB24.2 U102$CBB24.1 | length 104.2
  Top Layer w4.7: R211$CBB24.1@3176.5,4198.7 R212$CBB24.2@3176.5,4158.5 3203.1,4131.9 U102$CBB24.1@3203.1,4105.5
$4I280\$1N130253: R212$CBB24.1 U98$CBB24.61 U102$CBB24.3 | length 274.6
  Top Layer w4.7: R212$CBB24.1@3142.4,4158.5 3128.3,4144.4 U102$CBB24.3@3128.3,4105.5 3128.3,4069.2 3141.4,4056.1 3173.5,4056.1 3180.6,4063.2 U98$CBB24.61@3299.4,4063.2
$4I280\$1N130386: R214$CBB24.1 U98$CBB24.62 U102$CBB24.4 | length 229.1
  Top Layer w4.7: U102$CBB24.4@3128.3,3999.2 3128.3,4010.9 3163.8,4046.4 3177.5,4046.4 3179.2,4048.1 3193.6,4048.1 3197.6,4052.1 3227.7,4052.1 3236.3,4043.5 U98$CBB24.62@3299.4,4043.5
  Bottom Layer w11.8: R214$CBB24.1@3124.2,3976.3 3129.3,3981.4 v1(3129.3,3999.9)
$4I280\$1N130390: R213$CBB24.1 U98$CBB24.63 U102$CBB24.5 | length 196.5
  Top Layer w4.7: U102$CBB24.5@3165.7,3999.2 3165.7,4028.2 3173.5,4036 3230,4036 3242.2,4023.8 U98$CBB24.63@3299.4,4023.8
  Inner2 w11.8: v1(3165.5,3999.9) v1@3165.7,3999.6
  Bottom Layer w11.8: v1(3165.5,3999.9) 3169.2,3996.2 R213$CBB24.1@3169.2,3976.3
$4I280\$1N130504: C184$CBB24.2 U98$CBB24.3 U101$CBB24.1 | length 253.5
  Top Layer w4.7: U101$CBB24.1@3288.9,3756.6 3305.1,3756.6 C184$CBB24.2@3355.7,3807.2 3382.4,3807.2 3396.4,3821.2 3396.4,3844.4 3398.5,3846.6 3398.5,3860 3396.4,3862.2 3396.4,3877.4 3409.6,3890.6 U98$CBB24.3@3409.6,3933.3
$4I280\$1N130512: C185$CBB24.2 U98$CBB24.2 U101$CBB24.3 | length 289.4
  Top Layer w4.7: C185$CBB24.2@3160.7,3850.1 3167.6,3843.2 U101$CBB24.3@3222,3843.2 3262.2,3883.4 3374.3,3883.4 3389.9,3899.1 U98$CBB24.2@3389.9,3933.3
$4I280\$1N135657: R215$CBB24.2 U98$CBB24.7 | length 127.5
  Top Layer w4.7: R215$CBB24.2@3482.7,3808.1 3488.3,3813.7 U98$CBB24.7@3488.3,3933.3
$4I280\$1N135663: R217$CBB24.2 U98$CBB24.8 | length 131.4
  Top Layer w4.7: U98$CBB24.8@3508,3933.3 3508,3822.9 R217$CBB24.2@3522.9,3808.1
$4I280\$1N135820: R219$CBB24.2 U98$CBB24.6 | length 136.8
  Top Layer w4.7: R219$CBB24.2@3440.6,3808.1 3468.7,3836.2 U98$CBB24.6@3468.7,3933.3
$4I280\$1N136062: R179$CBB24.1 R181$CBB24.2 U98$CBB24.59 | length 159.6
  Top Layer w7.9: U98$CBB24.59@3299.4,4102.6 3362.5,4102.6 v1(3364.3,4104.3)
  Bottom Layer w4.7: v1(3364.3,4104.3) 3415.5,4104.3 R179$CBB24.1@3417.5,4106.2 R181$CBB24.2@3417.5,4066.1
$4I280\$1N136189: R220$CBB24.2 U98$CBB24.53 | length 130.4
  Top Layer w4.7: R220$CBB24.2@3176.5,4238.8 3193.6,4238.8 3205.6,4226.8 3237.8,4226.8 3243.9,4220.7 U98$CBB24.53@3299.4,4220.7
$4I280\$1N136261: R222$CBB24.2 U98$CBB24.28 | length 81.8
  Top Layer w7.9: U98$CBB24.28@3736.4,4220.7 3796.8,4220.7 R222$CBB24.2@3812,4235.8
$4I280\FTDI_RST: R218$CBB24.2 U98$CBB24.14 | length 205.4
  Top Layer w4.7: U98$CBB24.14@3626.1,3933.3 3626.1,3868.5 3657.4,3837.2 3679.8,3837.2 3705.6,3863.1 R218$CBB24.2@3705.6,3900.5
$4I280\P_CCK: U98$CBB24.16 U112$CBB24.1 | length 1026
  Top Layer w4.7: v1(3665.4,3869.4) 3665.4,3879.2 3665.5,3879.3 U98$CBB24.16@3665.5,3933.3
  Inner2 w4.7: v1(3717.6,3222.8) 3951.2,3222.8 U112$CBB24.1@3993.8,3180.2
  Inner4 w4.7: v1(3665.4,3869.4) 3665.4,3275 v1(3717.6,3222.8)
$4I280\P_CDI0: U98$CBB24.17 U112$CBB24.3 | length 974.2
  Top Layer w4.7: v1(3735.7,3957.7) 3736.4,3958.4 U98$CBB24.17@3736.4,4004.1
  Inner2 w4.7: v1(3737.7,3323.2) 3950.8,3323.2 U112$CBB24.3@3993.8,3280.2
  Inner4 w4.7: v1(3735.7,3957.7) 3759.8,3933.6 3759.8,3345.3 v1(3737.7,3323.2)
$4I280\P_CDI1: U98$CBB24.18 U112$CBB24.5 | length 960.2
  Top Layer w4.7: U98$CBB24.18@3736.4,4023.8 3778,4023.8 3779.9,4022 3779.9,3963.7 v1(3771.8,3955.6)
  Inner2 w4.7: v1(3776,3353.3) 3842.1,3353.3 3858.2,3337.3 3950.9,3337.3 U112$CBB24.5@3993.8,3380.2
  Inner4 w4.7: v1(3771.8,3955.6) 3771.8,3357.6 v1(3776,3353.3)
$4I280\P_CDI3: U2$CBB24.5 U98$CBB24.23 U111$CBB24.5 | length 694.8
  Top Layer w4.7: U98$CBB24.23@3736.4,4122.2 3839.3,4122.2 U2$CBB24.5@3893.8,4176.8
  Inner4 w4.7: U111$CBB24.5@3893.8,3710.2 3943.3,3759.7 3943.3,3861.8 3950.2,3868.8 3950.2,3973.2 3948.4,3975.1 3948.4,3988.5 3950.2,3990.4 3950.2,4110.3 3942.5,4118 3942.5,4128.1 U2$CBB24.5@3893.8,4176.8
$4I280\P_CONDONE: U2$CBB24.1 U98$CBB24.22 U111$CBB24.1 | length 630.7
  Top Layer w4.7: U98$CBB24.22@3736.4,4102.6 v1(3832.1,4102.6)
  Inner4 w4.7: U111$CBB24.1@3893.8,3910.2 3900.4,3916.8 3900.4,4005.9 3832.1,4074.2 v1(3832.1,4102.6) 3832.4,4102.9 3832.4,4335.5 3873.7,4376.8 U2$CBB24.1@3893.8,4376.8
$4I280\P_CRESET_N: U2$CBB24.3 U93$CBB24.5 U98$CBB24.21 U111$CBB24.3 | length 1821.7
  Top Layer w4.7: U98$CBB24.21@3736.4,4082.9 3838.8,4082.9 3878.3,4122.4 3904.4,4122.4 3946.5,4164.5 3946.5,4224.1 U2$CBB24.3@3893.8,4276.8
  Inner2 w7.9: U93$CBB24.5@3237.9,4660.9 3281.9,4616.9 3281.9,4521.9 3342.2,4461.7 3355.1,4461.7 3511.8,4305.1 3844.1,4305.1 3872.4,4276.8 U2$CBB24.3@3893.8,4276.8
  Inner4 w4.7: U111$CBB24.3@3893.8,3810.2 3893.8,3826.1 3940.5,3872.8 3940.5,3969.2 3938.7,3971.1 3938.7,3992.6 3940.5,3994.4 3940.5,4106.3 3910.8,4136 ; U2$CBB24.3@3893.8,4276.8 3842.1,4225.1 3842.1,4164.5 3870.2,4136.4 3876.4,4136.4 3876.9,4135.9 3910.7,4135.9
$4I280\P_SS: U98$CBB24.19 U112$CBB24.7 | length 779.2
  Top Layer w4.7: U98$CBB24.19@3736.4,4043.5 3772.4,4043.5 3795.9,4020 3795.9,3915.6 3848.1,3863.3 3926.5,3863.3 3927.8,3862 v1(3968,3862)
  Inner4 w4.7: v1(3968,3862) 3957.2,3862 3953,3857.8 3953,3593.3 3970,3576.4 3970,3504.1 U112$CBB24.7@3993.8,3480.2
$4I280\P_TCK: U1$CBB24.1 U93$CBB24.4 U98$CBB24.38 U110$CBB24.1 | length 1063.6
  Top Layer w4.7: v1(3565,4498) 3575.2,4498 3611.2,4534 3611.2,4586.2 3637.3,4612.3 3815,4612.3 U110$CBB24.1@3863.6,4660.9
  Top Layer w7.9: v1(3565,4498) 3567.1,4495.9 U98$CBB24.38@3567.1,4370.3
  Inner2 w7.9: U93$CBB24.4@3337.9,4560.9 3400.8,4498 v1(3565,4498)
  Inner4 w4.7: U110$CBB24.1@3863.6,4660.9 3912.4,4709.7 3912.4,4856.9 U1$CBB24.1@3863.6,4905.7
$4I280\P_TDI: U1$CBB24.3 U93$CBB24.3 U98$CBB24.39 U110$CBB24.3 | length 1183.7
  Top Layer w7.9: U93$CBB24.3@3337.9,4660.9 3390.5,4608.3 3472.7,4608.3 3494.8,4586.2 3494.8,4525.9 3547.4,4473.3 U98$CBB24.39@3547.4,4370.3
  Inner2 w7.9: U93$CBB24.3@3337.9,4660.9 3399.7,4722.7 3701.8,4722.7 U110$CBB24.3@3763.6,4660.9
  Inner4 w4.7: U110$CBB24.3@3763.6,4660.9 3763.6,4726.9 3719.6,4770.9 3719.6,4861.7 U1$CBB24.3@3763.6,4905.7
$4I280\P_TDO: U1$CBB24.5 U93$CBB24.2 U98$CBB24.40 U110$CBB24.5 | length 778.2
  Top Layer w7.9: U93$CBB24.2@3437.9,4560.9 3527.7,4471.1 U98$CBB24.40@3527.7,4370.3
  Inner2 w4.7: U93$CBB24.2@3437.9,4560.9 3449.4,4560.9 3494.8,4606.3 3609,4606.3 U110$CBB24.5@3663.6,4660.9
  Inner4 w4.7: U110$CBB24.5@3663.6,4660.9 3617.2,4707.3 3617.2,4851.2 3663.6,4897.6 U1$CBB24.5@3663.6,4905.7
$4I280\P_TMS: U1$CBB24.7 U93$CBB24.6 U98$CBB24.41 U110$CBB24.7 | length 1128.7
  Top Layer w4.7: U93$CBB24.6@3237.9,4560.9 3292,4615 3292,4690.6 3312,4710.7 3513.9,4710.7 U110$CBB24.7@3563.6,4660.9
  Top Layer w7.9: U93$CBB24.6@3237.9,4560.9 3329.1,4469.7 3486.7,4469.7 3508,4448.4 U98$CBB24.41@3508,4370.3
  Inner4 w4.7: U110$CBB24.7@3563.6,4660.9 3607.5,4704.8 3607.5,4861.8 U1$CBB24.7@3563.6,4905.7
$4I280\T120_CCK: U112$CBB24.2
$4I280\T120_CDI0: U112$CBB24.4
$4I280\T120_CDI1: U112$CBB24.6
$4I280\T120_CDI2: U111$CBB24.8
$4I280\T120_CDI3: U111$CBB24.6
$4I280\T120_CONDONE: U100$CBB22.N18 U111$CBB24.2 | length 2075.5
  Top Layer w4.7: v1(4531,4538) 4546.8,4553.9 4549,4553.9 4714,4718.9 4792.3,4718.9 4826.4,4753 4847.4,4753 4859.2,4764.8 4863.7,4764.8 4867.1,4768.2 4867.1,4789.7 4865.1,4791.7 4872.2,4798.7 5050.9,4798.7 5075.3,4774.3 5075.3,4774 5130.4,4718.9 5130.7,4718.9 5140.9,4708.6 5140.9,4703.5 5146.9,4697.5 5146.9,4688.6 5187.8,4647.8 U100$CBB22.N18@5260.4,4647.8
  Inner2 w4.7: v1(4037.7,4493.1) 4051,4506.4 4061.5,4506.4 4071.8,4516.7 4149.7,4516.7 4150.6,4515.7 4164.1,4515.7 4165,4516.7 4309.9,4516.7 4319.3,4526.1 4332.7,4526.1 4342.1,4516.7 4509.7,4516.7 v1(4531,4538)
  Inner4 w4.7: U111$CBB24.2@3993.8,3910.2 4037.3,3910.2 4041.9,3914.9 4041.9,4408.5 4037.7,4412.7 v1(4037.7,4493.1)
$4I280\T120_CRESET_N: U100$CBB22.N17 U111$CBB24.4 | length 2204.3
  Top Layer w4.3: 5250.9,4634.8 5251.2,4635.2 5273.3,4635.2 U100$CBB22.N17@5285.9,4647.8
  Top Layer w4.7: v1(4546.1,4519.7) 4555.9,4529.5 4555.9,4547 4718.1,4709.2 4796.4,4709.2 4830.5,4743.3 4851.4,4743.3 4863.2,4755.1 4867.8,4755.1 4876.8,4764.2 4876.8,4789 5046.9,4789 5065.6,4770.2 5065.6,4769.9 5126.4,4709.2 5126.7,4709.2 5131.2,4704.6 5131.2,4699.5 5137.2,4693.5 5137.2,4684.6 5187,4634.8 5250.9,4634.8
  Inner2 w4.7: v1(4055.1,4475.7) 4068.4,4489 4068.4,4499.5 4075.9,4507 4145.7,4507 4146.6,4506 4168.1,4506 4169.1,4507 4309.8,4507 4309.8,4503.2 4319.3,4493.7 4332.7,4493.7 4342.2,4503.2 4342.2,4507 4515.9,4507 4518.7,4509.8 4536.3,4509.8 v1(4546.1,4519.7)
  Inner4 w4.7: U111$CBB24.4@3993.8,3810.2 4041.3,3810.2 4051.6,3820.6 4051.6,4472.2 v1(4055.1,4475.7)
$4I280\T120_SS: U112$CBB24.8
$4I280\T120_TCK: U100$CBB22.T16 U110$CBB24.2 | length 1779.9
  Top Layer w4.7: v1(4484.6,4805) 4494.7,4805 4516.8,4783 4528,4783 4528.1,4782.8 4541.6,4782.8 4541.7,4783 4756.7,4783 v1(4771.8,4798)
  Inner2 w4.7: v1(3930.3,4805) v1(4484.6,4805) ; v1(4771.8,4798) 4792.6,4798 4809.2,4814.6 4813.5,4814.6 4821.3,4822.5 5082.2,4822.5 5098.9,4839.2 5183.4,4839.2 5207.5,4815.1 5207.5,4808.4 5220.7,4795.2 5224.2,4795.2 5233.7,4785.7 5233.7,4782.2 5291.4,4724.5 v2(5311.5,4724.5)
  Inner4 w4.7: U110$CBB24.2@3863.6,4560.9 3868.5,4556.1 3921.8,4556.1 3930.3,4564.6 v1(3930.3,4805)
$4I280\T120_TDI: U100$CBB22.R16 U110$CBB24.4 | length 1813.3
  Top Layer w4.7: v1(4534.8,4636.4) 4577,4678.5 4577,4687.3 4586.5,4696.8 4595.2,4696.8 4663.3,4764.9 4763.7,4764.9 v1(4771.8,4772.9)
  Inner2 w4.7: U110$CBB24.4@3763.6,4560.9 3763.6,4556.3 3806,4513.9 3951.2,4513.9 4032.8,4595.6 4494.1,4595.6 4516.8,4618.4 4516.8,4618.9 4526.3,4628.4 4526.9,4628.4 v1(4534.8,4636.4) ; v1(4771.8,4772.9) 4785.8,4772.9 4798,4785.1 4798,4789.7 4813.2,4804.9 4817.8,4804.9 4825.7,4812.8 5086.7,4812.8 5103.1,4829.1 5176.2,4829.1 5185.6,4819.8 5185.6,4803.4 5180.5,4798.4 5180.5,4785 5181.2,4784.3 5181.2,4745 5227.2,4698.9 v2(5311.5,4698.9)
$4I280\T120_TDO: U100$CBB22.P17 U110$CBB24.6 | length 1865.2
  Top Layer w4.3: 5250.9,4660.4 5251.2,4660.7 5273.3,4660.7 U100$CBB22.P17@5285.9,4673.3
  Top Layer w4.7: v1(4533.1,4612.2) 4593.6,4612.2 4710,4728.6 4788.3,4728.6 4822.4,4762.7 4843.3,4762.7 4855.2,4774.6 4857.4,4774.6 4857.4,4785.7 4851.4,4791.7 4868.1,4808.4 5054.9,4808.4 5085,4778.3 5085,4778 5134.4,4728.6 5134.7,4728.6 5150.7,4712.7 5150.7,4707.5 5156.7,4701.6 5156.7,4693.2 5189.5,4660.4 5250.9,4660.4
  Inner2 w4.7: U110$CBB24.6@3663.6,4560.9 3674.6,4560.9 3731.7,4503.9 3954.9,4503.9 4036.9,4585.9 4506.7,4585.9 v1(4533.1,4612.2)
$4I280\T120_TMS: U100$CBB22.P16 U110$CBB24.8 | length 1977.5
  Top Layer w4.7: v1(4575.2,4628.7) 4579.5,4624.3 4583.3,4624.3 4634.8,4675.8 4634.8,4697.3 4634.4,4697.7 4685.8,4749.2 v1(4771.8,4749.2)
  Inner2 w4.7: U110$CBB24.8@3563.6,4560.9 3630.4,4494.1 3958.9,4494.1 4040.9,4576.1 4520.8,4576.1 4545.4,4600.8 4545.4,4601.6 4572.5,4628.7 v1(4575.2,4628.7) ; v1(4771.8,4749.2) 4785.7,4763.2 4789.9,4763.2 4807.8,4781.1 4807.8,4785.7 4817.3,4795.2 4821.8,4795.2 4829.7,4803 5066.6,4803 5196.3,4673.3 v2(5311.5,4673.3)
$4I280\USB_D_N: D1$CBB24.3 R215$CBB24.1 USB3$CBB24.2 | length 812.9
  Top Layer w4.7: R215$CBB24.1@3482.7,3774 3482.7,3758.2 3496.5,3744.4 3496.5,3734.4 3494.2,3732.2 3494.2,3725.6 3531.7,3688.1 3676.9,3688.1 3693,3672 3693,3667.3 3667.1,3641.5 3667.1,3636.8 3681.9,3622 3686.6,3622 3712.5,3647.8 3717.2,3647.8 3732.4,3632.6 3732.4,3627.9 3731.7,3627.1 3731.7,3612.4 3702.3,3583 D1$CBB24.3@3702.3,3571.3 3702.3,3532.1 3696.9,3526.7 3674.3,3526.7 3663.5,3516 3663.5,3421.5 3644.5,3402.4 3582,3402.4 3576,3408.4 3596.3,3428.8 3598.8,3428.8 3609.6,3439.5 USB3$CBB24.2@3609.6,3444.7
$4I280\USB_D_P: D1$CBB24.1 R217$CBB24.1 USB3$CBB24.3 | length 813.9
  Top Layer w4.7: R217$CBB24.1@3522.9,3774 3522.9,3758.2 3509.1,3744.4 3509.1,3734.4 3506.8,3732.2 3506.8,3730.8 3536.9,3700.7 3682.1,3700.7 3745,3637.8 3745,3627.9 3745.7,3627.1 3745.7,3612.4 3777.1,3581 D1$CBB24.1@3777.1,3571.3 3777.1,3566.7 3753.2,3542.8 3730.8,3542.8 3702.1,3514.1 3679.5,3514.1 3676.1,3510.7 3676.1,3416.3 3649.7,3389.8 3576.8,3389.8 3563.4,3403.2 3563.4,3407 3530.8,3439.5 USB3$CBB24.3@3530.8,3444.7
$6N19: C45.2 R60.1 R127.2 U10.2 | length 152.6
  Top Layer w7.9: C45.2@3807.9,8009.6 3826,8009.6 3840.4,7995.2 R127.2@3852.9,7995.2 R60.1@3892.9,7995.2 3892.9,8018.2 3902.7,8028 U10.2@3902.7,8052.8
$6N23: R126.1 U10.3 | length 59.5
  Top Layer w7.9: U10.3@3928.3,8052.8 3928.5,8052.6 3928.5,7999.6 R126.1@3932.9,7995.2
$6N67: C33.2 U9.1 | length 42.4
  Top Layer w11: v1(3585.1,6490) 3585.1,6448.7 U9.1@3585.9,6447.9
$6N70: C40.2 U9.7 | length 58.4
  Top Layer w11: U9.7@3636.3,6428.2 3694.5,6428.2 C40.2@3694.7,6428.3
$6N72: R57.1 U9.8 | length 68.3
  Top Layer w11: U9.8@3636.3,6447.9 3653.4,6447.9 3678.9,6473.3 R57.1@3694.1,6473.3
$6N73: C34.1 R56.1 R57.2 R59.2 | length 152.2
  Top Layer w11.8: R57.2@3728.2,6473.3 3746.1,6491.3 R56.1@3746.1,6521.3 3790.6,6521.3 C34.1@3791.1,6521.9 R59.2@3791.1,6470.4
$6N74: R96.2 U9.5 | length 60.4
  Top Layer w11: U9.5@3636.3,6388.8 3654.2,6388.8 3667.6,6375.4 R96.2@3691.1,6375.4
$6N75: C41.2 R96.1 | length 54.8
  Top Layer w11.8: C41.2@3637.6,6338.3 3688.2,6338.3 R96.1@3691.1,6341.3
$6N79: C34.2 C39.2 L4.1 R56.2 R58.2 | length 477
  Top Layer w11.8: v1(3746.1,6602.3) R56.2@3746.1,6555.4 3768.9,6555.4 3778.3,6564.8 C34.2@3791.1,6564.8
  Inner2 w11.8: v1(3376.8,6573.3) 3413.4,6573.3 3442.6,6602.5 v1@3745.9,6602.5
$6N82: C41.1 L4.2 U9.3 | length 328.3
  Top Layer w11: L4.2@3388.6,6339.8 3488.3,6339.8 3553,6404.5 ; 3557,6408.5 U9.3@3585.9,6408.5
  Top Layer w11.8: 3557,6408.5 3553,6404.5 3553,6347.5 3562.1,6338.3 C41.1@3594.7,6338.3
$6N84: C48.2 U12.1 | length 42.5
  Top Layer w11: v1(3585.1,7001.9) 3585.1,6960.5 U12.1@3585.9,6959.7
$6N87: C54.2 U12.7 | length 58.5
  Top Layer w11: U12.7@3636.3,6940 3694.5,6940 C54.2@3694.7,6940.2
$6N89: R131.1 U12.8 | length 68.4
  Top Layer w11: U12.8@3636.3,6959.7 3653.4,6959.7 3678.9,6985.2 R131.1@3694.1,6985.2
$6N90: C49.1 R129.1 R131.2 R133.2 | length 152.1
  Top Layer w11.8: R131.2@3728.2,6985.2 3746.1,7003.1 R129.1@3746.1,7033.1 3790.6,7033.1 C49.1@3791.1,7033.7 R133.2@3791.1,6982.2
$6N91: R135.2 U12.5 | length 60.4
  Top Layer w11: U12.5@3636.3,6900.6 3654.2,6900.6 3667.6,6887.2 R135.2@3691.1,6887.2
$6N92: C57.2 R135.1 | length 54.7
  Top Layer w11.8: C57.2@3637.6,6850.2 3688.2,6850.2 R135.1@3691.1,6853.1
$6N96: C49.2 C53.2 L5.1 R129.2 R132.2 | length 479.2
  Top Layer w11.8: v1(3747.5,7114.1) 3746.1,7112.8 R129.2@3746.1,7067.2 3768.9,7067.2 3778.3,7076.6 C49.2@3791.1,7076.6
  Inner2 w11.8: v1(3376.8,7085.2) 3413.4,7085.2 3442.6,7114.3 3747.3,7114.3 v1(3747.5,7114.1)
$6N99: C57.1 L5.2 U12.3 | length 328.2
  Top Layer w11: L5.2@3388.6,6851.6 3488.3,6851.6 3553,6916.3 ; 3557,6920.3 U12.3@3585.9,6920.3
  Top Layer w11.8: 3557,6920.3 3553,6916.3 3553,6859.3 3562.1,6850.2 C57.1@3594.7,6850.2
$6N100: C64.2 U16.1 | length 42.5
  Top Layer w11: v1(3585.1,7513.7) 3585.1,7472.3 U16.1@3585.9,7471.5
$6N103: C68.2 U16.7 | length 58.5
  Top Layer w11: U16.7@3636.3,7451.8 3694.5,7451.8 C68.2@3694.7,7452
$6N107: R145.1 U16.8 | length 68.4
  Top Layer w11: U16.8@3636.3,7471.5 3653.4,7471.5 3678.9,7497 R145.1@3694.1,7497
$6N108: C65.1 R143.1 R145.2 R147.2 | length 152.1
  Top Layer w11.8: R145.2@3728.2,7497 3746.1,7514.9 R143.1@3746.1,7544.9 3790.6,7544.9 C65.1@3791.1,7545.5 R147.2@3791.1,7494
$6N109: R149.2 U16.5 | length 60.4
  Top Layer w11: U16.5@3636.3,7412.4 3654.2,7412.4 3667.6,7399 R149.2@3691.1,7399
$6N110: C70.2 R149.1 | length 54.7
  Top Layer w11.8: C70.2@3637.6,7362 3688.2,7362 R149.1@3691.1,7364.9
$6N113: C65.2 C66.2 L7.1 R143.2 R146.2 | length 572.8
  Top Layer w11.8: R143.2@3746.1,7579 3768.9,7579 3778.3,7588.4 C65.2@3791.1,7588.4 3820.5,7588.4 v1(3832.1,7600)
  Inner2 w11.8: v1(3376.8,7597) 3413.4,7597 3442.6,7626.1 3806,7626.1 v1(3832.1,7600)
$6N116: C70.1 L7.2 U16.3 | length 328.2
  Top Layer w11: L7.2@3388.6,7363.4 3488.3,7363.4 3553,7428.1 ; 3557,7432.1 U16.3@3585.9,7432.1
  Top Layer w11.8: 3557,7432.1 3553,7428.1 3553,7371.1 3562.1,7362 C70.1@3594.7,7362
$6N141: C2.2 C81.1 D19.1 L1.1 | length 980.7
  Top Layer w19.7: C2.2@3478.2,8965.4 3550.5,9037.6 3697.6,9037.6 3715.6,9019.6 3908.4,9019.6 3924.4,9035.6 3972.6,9035.6 3994.7,9013.5 4053,9013.5 4073,8993.5 4338.5,8993.5 C81.1@4380.2,8951.8
$6N142: LED2.2 R54.1 | length 51.9
  Top Layer w7.9: LED2.2@3149.4,8091.8 3151.4,8093.8 R54.1@3151.4,8142.9
$6N144: LED1.2 R51.1 | length 52.2
  Top Layer w11.8: R51.1@3498.6,9456.7 3498.6,9408.4 LED1.2@3501.4,9405.7
$6N147: D19.2 U3.1
$6N151: R151.2 U7.4 | length 66.8
  Top Layer w11.8: U7.4@3452.6,7788.7 3473.7,7767.6 R151.2@3473.7,7730.6
$6N152: R150.2 U6.4 | length 59.6
  Top Layer w11.8: U6.4@3825,9105.6 3828.5,9102 R150.2@3828.5,9047.4
$6N165: C3.2 C4.2 C7.2 C35.2 C72.2 C83.1 L1.2 U5.2 U6.2 U6.3 U7.2 | length 764.4
  Top Layer w31.5: C35.2@3352.3,7870.6 3352.3,7736.4 3412.4,7676.3 3472.7,7676.3 3490.7,7658.2 C83.1@3950.1,7658.2
  other v1: 3285.9,7810.8 3285.9,7857 3285.9,7901.2 3285.9,7945.4 3350.2,8288.7 3350.2,8338.9 3350.2,8393.1 3872.9,8433.6 3350.2,8443.3 3872.9,8465.8 3872.9,8497.9 3872.9,8528 3350.2,8533.7 3350.2,8583.9 3350.2,8638.1 3350.2,8688.3 3337.9,8798.5 3273.8,8798.6 3305.9,8798.6 3273.9,8830.8 3305.9,8830.7 3337.9,8830.6 3273.8,8862.8 3305.9,8862.8 3337.9,8862.7 3661.4,9099.9 3661.4,9152.1 3661.4,9200.3 3661.4,9252.5
$6N170: LED3.2 R61.1 | length 51
  Top Layer w7.9: LED3.2@3456.6,8461.3 R61.1@3456.6,8512.3
$6N182: C55.1 L3.1 U7.8 | length 85.3
  Top Layer w11.8: C55.1@3592.2,7990.6 3677.5,7990.6
$6N183: C55.2 U7.1 | length 118.2
  Top Layer w11.8: U7.1@3452.6,7938.7 3504.5,7990.6 C55.2@3549.3,7990.6
$6N184: C59.1 L2.1 U6.8 | length 120.6
  Top Layer w11.8: C59.1@3962,9307.4 4009.3,9307.4 U6.8@4061.2,9255.6
$6N185: C58.2 R52.2 U6.6 | length 115.4
  Top Layer w11.8: U6.6@4061.2,9155.6 4106.6,9155.6 4112.7,9161.6 C58.2@4127.3,9161.6 4143.8,9161.6 4149.8,9155.7 R52.2@4171.7,9155.7
$6N187: C56.2 R52.1 | length 43.3
  Top Layer w11.8: C56.2@4203.8,9198.2 4205.8,9196.2 R52.1@4205.8,9155.7
$6N190: R55.2 R125.2 U6.5 | length 118.2
  Top Layer w11.8: U6.5@4061.2,9105.6 4120.4,9105.6 R55.2@4123.5,9102.4 4113.2,9092.1 4113.2,9053 R125.2@4112.6,9052.4
$6N193: C59.2 U6.1 | length 115.6
  Top Layer w11.8: U6.1@3825,9255.6 3841.7,9255.6 3893.5,9307.4 C59.2@3919.1,9307.4
$6N196: C62.2 R136.1 | length 45.2
  Top Layer w11.8: C62.2@3832.3,7885.6 3832.8,7885.1 R136.1@3832.8,7840.6
$6N197: C69.2 R136.2 U7.6 | length 117.7
  Top Layer w11.8: U7.6@3688.8,7838.7 3740.4,7838.7 C69.2@3750.7,7849 3763.8,7849 3771.8,7840.9 3798.3,7840.9 R136.2@3798.7,7840.6
$6N199: R130.2 R134.2 U7.5 | length 125.5
  Top Layer w11.8: R134.2@3692.8,7730.6 3692.8,7784.8 U7.5@3688.8,7788.7 3751.8,7788.7 R130.2@3753.7,7790.6
$6N204: C73.2 R138.1 | length 45.2
  Top Layer w11.8: C73.2@3852.9,8987.9 3897.4,8987.9 R138.1@3897.9,8988.4
$6N205: C74.2 R138.2 U5.6 | length 115.4
  Top Layer w11.8: R138.2@3894.6,8952.5 3894.6,8930.6 3888.7,8924.6 3888.7,8893.5 3894.7,8887.4 U5.6@3894.7,8842
$6N206: C36.2 U5.1 | length 115.6
  Top Layer w11.8: C36.2@3742.9,8699.9 3742.9,8674.3 3794.7,8622.4 U5.1@3794.7,8605.7
$6N207: C36.1 L6.1 U5.8 | length 96.4
  Top Layer w11.8: C36.1@3742.9,8742.8 3742.9,8838 3743.7,8838.9
$6N210: R141.2 U5.4 | length 59.7
  Top Layer w11.8: U5.4@3944.7,8605.7 3948.3,8609.3 R141.2@4002.9,8609.3
$6N216: R137.2 R142.2 R144.1 U5.5 | length 203.1
  Top Layer w7.9: R137.2@4002.8,8936.3 4017.8,8936.3 4030.9,8923.2 R144.1@4056,8923.2
  Top Layer w11.8: U5.5@3944.7,8842 3944.7,8906.2 R142.2@3947.9,8909.3 3992.4,8909.3 4002.8,8919.6 R137.2@4002.8,8936.3
ACT(4)_D_ROW1: Q5$CBB9/CBB1.3 Q5$CBB9/CBB7.3 Q5$CBB9/CBB13.3 Q5$CBB9/CBB19.3 Q5$CBB9/CBB25.3 Q5$CBB9/CBB31.3 Q8$CBB9/CBB1.3 Q8$CBB9/CBB7.3 Q8$CBB9/CBB13.3 Q8$CBB9/CBB19.3 Q8$CBB9/CBB25.3 Q8$CBB9/CBB31.3 R14$CBB1.2 U1$CBB1.14 | length 8003.8
  Top Layer w7.9: Q5$CBB9/CBB1.3@7648.6,8973.7 7676.2,8973.7 7686.2,8983.7 v1@7686.2,9043.7 ; Q8$CBB9/CBB1.3@7648.6,9058.7 7673.7,9058.7 v1(7688.7,9043.7) ; v1(7692.1,4992.2) U1$CBB1.14@7756.1,4992.2 7802.1,4992.2 7812.1,4982.2 7825.1,4982.2 R14$CBB1.2@7827.1,4984.2 ; Q5$CBB9/CBB7.3@8157.3,8973.7 8184.9,8973.7 8194.9,8983.7 v1@8194.9,9043.7 ; Q8$CBB9/CBB7.3@8157.3,9058.7 8182.4,9058.7 v1(8197.4,9043.7) ; Q5$CBB9/CBB13.3@8666,8973.7 8693.6,8973.7 8703.6,8983.7 v1@8703.6,9043.7 ; Q8$CBB9/CBB13.3@8666,9058.7 8691.1,9058.7 v1(8706.1,9043.7) ; Q5$CBB9/CBB19.3@9174.7,8973.7 9202.3,8973.7 9212.3,8983.7 v1@9212.3,9043.7 ; Q8$CBB9/CBB19.3@9174.7,9058.7 9199.8,9058.7 v1(9214.8,9043.7) ; Q5$CBB9/CBB25.3@9683.4,8973.7 9711,8973.7 9721,8983.7 v1@9721,9043.7 ; Q8$CBB9/CBB25.3@9683.4,9058.7 9708.5,9058.7 v1(9723.5,9043.7) ; Q5$CBB9/CBB31.3@10192.1,8973.7 10219.7,8973.7 10229.7,8983.7 v1@10229.7,9043.7 ; Q8$CBB9/CBB31.3@10192.1,9058.7 10217.2,9058.7 v1(10232.2,9043.7)
  Inner2 w7.9: v1(7326.2,9043.7) v1(7688.7,9043.7) v1(8197.4,9043.7) v1(8706.1,9043.7) v1(9214.8,9043.7) v1(9723.5,9043.7) v1(10232.2,9043.7)
  Inner4 w7.9: v1(7688.7,9043.7) 7712.1,9020.3 7712.1,5062 7692.1,5042 v1(7692.1,4992.2)
ACT(4)_D_ROW2: Q5$CBB9/CBB2.3 Q5$CBB9/CBB8.3 Q5$CBB9/CBB14.3 Q5$CBB9/CBB20.3 Q5$CBB9/CBB26.3 Q5$CBB9/CBB32.3 Q8$CBB9/CBB2.3 Q8$CBB9/CBB8.3 Q8$CBB9/CBB14.3 Q8$CBB9/CBB20.3 Q8$CBB9/CBB26.3 Q8$CBB9/CBB32.3 R14$CBB2.2 U1$CBB2.14 | length 7465.3
  Top Layer w7.9: Q5$CBB9/CBB2.3@7648.6,8453.7 7676.2,8453.7 7686.2,8463.7 v1@7686.2,8523.7 ; Q8$CBB9/CBB2.3@7648.6,8538.7 7673.7,8538.7 v1(7688.7,8523.7) ; Q5$CBB9/CBB8.3@8157.3,8453.7 8184.9,8453.7 8194.9,8463.7 v1@8194.9,8523.7 ; Q8$CBB9/CBB8.3@8157.3,8538.7 8182.4,8538.7 v1(8197.4,8523.7) ; v1(8227.9,5018) 8253.7,4992.2 U1$CBB2.14@8264.8,4992.2 8310.8,4992.2 8320.8,4982.2 8333.8,4982.2 R14$CBB2.2@8335.8,4984.2 ; Q5$CBB9/CBB14.3@8666,8453.7 8693.6,8453.7 8703.6,8463.7 v1@8703.6,8523.7 ; Q8$CBB9/CBB14.3@8666,8538.7 8691.1,8538.7 v1(8706.1,8523.7) ; Q5$CBB9/CBB20.3@9174.7,8453.7 9202.3,8453.7 9212.3,8463.7 v1@9212.3,8523.7 ; Q8$CBB9/CBB20.3@9174.7,8538.7 9199.8,8538.7 v1(9214.8,8523.7) ; Q5$CBB9/CBB26.3@9683.4,8453.7 9711,8453.7 9721,8463.7 v1@9721,8523.7 ; Q8$CBB9/CBB26.3@9683.4,8538.7 9708.5,8538.7 v1(9723.5,8523.7) ; Q5$CBB9/CBB32.3@10192.1,8453.7 10219.7,8453.7 10229.7,8463.7 v1@10229.7,8523.7 ; Q8$CBB9/CBB32.3@10192.1,8538.7 10217.2,8538.7 v1(10232.2,8523.7)
  Inner2 w7.9: v1(7326.2,8523.7) v1(7688.7,8523.7) v1(8197.4,8523.7) v1(8706.1,8523.7) v1(9214.8,8523.7) v1(9723.5,8523.7) v1(10232.2,8523.7)
  Inner4 w7.9: v1(8197.4,8523.7) 8217.1,8504 8217.1,8376.7 8217.7,8376.1 8217.7,7951.4 8217.1,7950.8 8217.1,7591.7 8217.7,7591.1 8217.7,7166.4 8217.1,7165.8 8217.1,6806.7 8217.7,6806.1 8217.7,6791.4 8217.1,6790.8 8217.1,6661.7 8217.7,6661.1 8217.7,5486.4 8217.1,5485.8 8217.1,5305.6 8229,5293.7 8236,5293.7 8246.4,5283.3 8246.4,5269.5 8252.1,5263.7 8252.1,5258.8 8255.7,5255.2 8255.7,5227.3 8227.9,5199.5 v1(8227.9,5018)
